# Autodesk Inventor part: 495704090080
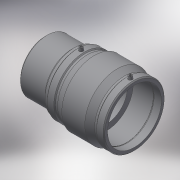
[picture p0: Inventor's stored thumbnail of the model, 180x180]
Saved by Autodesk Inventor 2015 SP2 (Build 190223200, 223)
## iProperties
Created: 2017-06
Part Number: 495704090080
Material: Generic
Description: PLASSON PE CAST IRON SPIGOT COUPLER TRANSITION 90-80
Document SubType Name: Modeling
Designer: KIM
Mass: 55.0731 g
Surface Area: 148.067 cm^2
Volume: 55.0731 cm^3
Density: 1 g/cm^3
Appearance: Default
Author: KIM
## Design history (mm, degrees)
derived "495704.ipt"
feature "Solid1::495704.ipt"
tag "TaggingFeature1"
body "Solid1"
other parameters: "d13" = 148, "d14" = 17.6296, "d15" = 73, "d16" = 73, "d17" = 85.5, "d19" = 3.52592, "d20" = 168 deg, "d22" = 105.28, "d23" = 112, "d24" = 102.1216, "d25" = 135 deg, "d26" = 59.2, "d27" = 135 deg, "d29" = 69, "d35" = 15, "d39" = 5 deg, "d45" = 4, "d46" = 14, "d47" = 0, "d50" = 3, "d51" = 0, "d52" = 21.17, "d53" = 5.2925, "d54" = 98, "d55" = 0.1, "d56" = 107.8, "d57" = 94, "d58" = 106, "d60" = 67, "d62" = 2.94, "d65" = 4.9, "L_" = 254, "L_1" = 73, "D_1" = 112, "A_" = 69, "d_2" = 12, "L_2" = 106, "H_" = 94, "D_" = 98, "d_1" = 67
